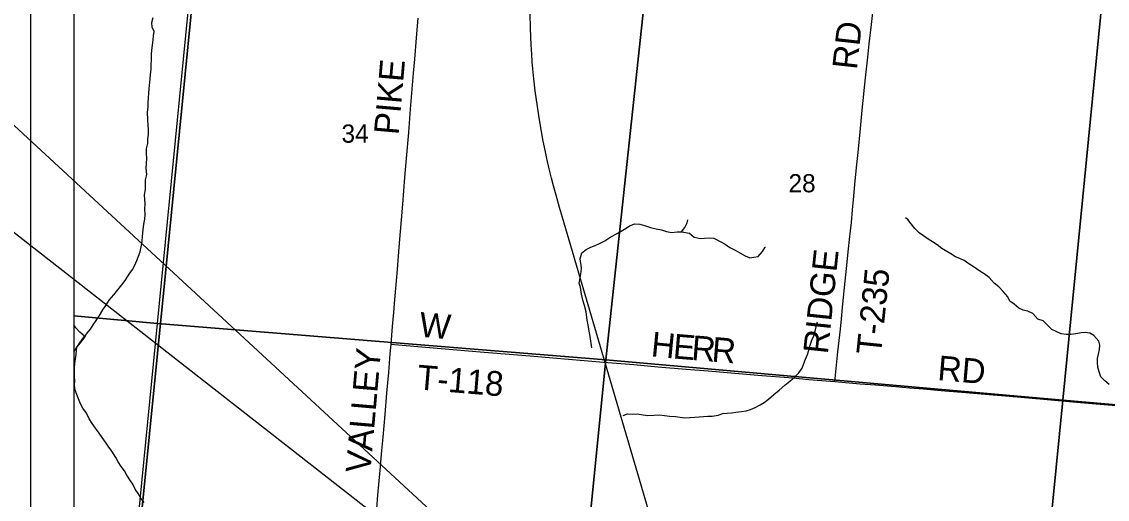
# Model space of a CAD drawing. Extents: x 831 to 1552, y 430 to 870.
# Drawn here: x 943.37 to 993.28, y 692.99 to 714.97 of the extents above; entities that cross this region are included whole.
import ezdxf

# ---------------------------------------------------------------- set-up
doc = ezdxf.new("R2010")
doc.units = 0
for name, color, linetype in [('GM_X_Corporation', 7, 'Continuous'), ('GM_X_County_Road', 7, 'Continuous'), ('GM_X_County_Road_Text', 7, 'Continuous'), ('GM_X_Major_River', 7, 'Continuous'), ('GM_X_Minor_River', 7, 'Continuous'), ('GM_X_Rail_Line', 7, 'Continuous'), ('GM_X_Section_Text', 7, 'Continuous'), ('GM_X_Township_Road', 7, 'Continuous'), ('GM_X_Township_Road_Text', 7, 'Continuous'), ('SH_Data', 7, 'Continuous'), ('SH_Text', 7, 'Continuous')]:
    doc.layers.add(name, color=color, linetype=linetype)

msp = doc.modelspace()

# ---------------------------------------------------------------- linework, layer by layer
at = {"layer": 'GM_X_Corporation'}
msp.add_lwpolyline([(957.479, 781.045), (956.56, 771.006), (955.451, 760.717), (953.653, 740.871), (952.689, 730.885), (949.971, 703.401), (947.763, 681.071), (945.766, 658.183), (945.766, 650.938), (1069.909, 650.938), (1070.34, 654.531), (1072.813, 675.454), (1078.126, 715.958), (1081.227, 740.59), (1081.766, 744.853), (1081.766, 786.938)], dxfattribs=at)
for points in [[(945.766, 741.831), (945.766, 658.183), (947.763, 681.071), (949.971, 703.401), (952.689, 730.885), (953.653, 740.871)], [(945.766, 721.457), (945.766, 701.429), (949.612, 701.081), (951.55, 720.891)], [(972.322, 718.961), (970.228, 699.411), (949.612, 701.081), (951.55, 720.891)], [(993.147, 717.069), (991.236, 697.554), (970.228, 699.411), (972.322, 718.961)], [(993.147, 717.069), (1013.944, 715), (1011.587, 695.769), (991.236, 697.554)], [(945.766, 701.429), (945.766, 681.274), (947.656, 681.105), (949.612, 701.081)], [(970.228, 699.411), (968.2, 679.179), (947.656, 681.105), (949.612, 701.081)], [(970.228, 699.411), (991.236, 697.554), (989.239, 677.411), (968.2, 679.179)], [(1011.587, 695.769), (1009.676, 675.38), (989.239, 677.411), (991.236, 697.554)]]:
    msp.add_lwpolyline(points, close=True, dxfattribs=at)
at = {"layer": 'GM_X_County_Road'}
for points in [[(960.352, 700.134), (960.421, 700.945), (960.476, 701.589), (960.526, 702.183), (960.597, 703.038), (960.64, 703.571), (960.72, 704.599), (960.883, 706.572), (960.985, 707.802), (961.06, 708.677), (961.159, 709.877), (961.244, 710.945), (961.379, 712.6), (961.435, 713.237), (961.517, 714.233), (961.591, 715.127)], [(959.689, 692.563), (959.744, 693.182), (959.843, 694.327), (959.924, 695.237), (959.982, 695.856), (960.07, 696.896), (960.155, 697.874), (960.239, 698.828), (960.314, 699.682), (960.352, 700.134)]]:
    msp.add_lwpolyline(points, dxfattribs=at)
at = {"layer": 'GM_X_Major_River'}
for points in [[(945.904, 699.985), (946.076, 700.198), (946.234, 700.399), (946.353, 700.6), (946.527, 700.823), (946.654, 701.024), (946.797, 701.218), (946.94, 701.456), (947.092, 701.71), (947.242, 701.911), (947.394, 702.157), (947.606, 702.401), (947.794, 702.623), (947.976, 702.853), (948.118, 703.062), (948.302, 703.352), (948.46, 703.56), (948.564, 703.77), (948.662, 703.987), (948.81, 704.377), (948.862, 704.603), (948.9, 704.86), (948.915, 705.102), (948.946, 705.39), (948.984, 705.647), (949.022, 705.888), (949.043, 706.1), (949.035, 706.336), (949.05, 706.593), (949.026, 706.791), (949.016, 706.996), (949.062, 707.253), (949.054, 707.495), (949.052, 707.693), (949.113, 707.941), (949.091, 708.222), (949.097, 708.45), (949.12, 708.692), (949.111, 708.897), (949.11, 709.124), (949.17, 709.358), (949.169, 709.585), (949.198, 709.781), (949.197, 710.001), (949.18, 710.214), (949.164, 710.449), (949.145, 710.806), (949.174, 711.04), (949.187, 711.229), (949.202, 711.464), (949.208, 711.676), (949.222, 711.88), (949.266, 712.334), (949.287, 712.538), (949.317, 712.772), (949.315, 712.961), (949.337, 713.211), (949.329, 713.453), (949.35, 713.657), (949.373, 713.892), (949.41, 714.133), (949.431, 714.322), (949.452, 714.518), (949.367, 714.71), (949.343, 714.93), (949.41, 715.163)], [(945.904, 699.985), (945.856, 699.947), (945.766, 699.759)], [(948.994, 692.849), (948.848, 693.043), (948.725, 693.26), (948.587, 693.462), (948.472, 693.685), (948.342, 693.894), (948.204, 694.096), (948.088, 694.305), (947.935, 694.507), (947.804, 694.716), (947.696, 694.909), (947.508, 695.211), (947.34, 695.429), (947.224, 695.622), (947.071, 695.832), (946.925, 696.041), (946.757, 696.259), (946.604, 696.484), (946.474, 696.693), (946.345, 696.947), (946.17, 697.188), (946.069, 697.381), (945.985, 697.611), (945.9, 697.819), (945.822, 698.019), (945.798, 698.224), (945.804, 698.444), (945.795, 698.642), (945.801, 698.855), (945.792, 699.045), (945.813, 699.242), (945.834, 699.454), (945.87, 699.658), (945.884, 699.847), (945.904, 699.985)]]:
    msp.add_lwpolyline(points, dxfattribs=at)
at = {"layer": 'GM_X_Minor_River'}
for points in [[(973.697, 705.303), (973.85, 705.505), (973.955, 705.706), (973.989, 705.85)], [(993.355, 698.278), (993.163, 698.435), (992.986, 698.631), (992.902, 698.861), (992.847, 699.075), (992.831, 699.281), (992.829, 699.471), (992.865, 699.675), (992.917, 699.879), (992.93, 700.076), (992.883, 700.275), (992.662, 700.524), (992.468, 700.629), (992.264, 700.665), (992.074, 700.656), (991.83, 700.61), (991.616, 700.571), (991.381, 700.57), (991.154, 700.607), (990.93, 700.713), (990.728, 700.81), (990.514, 701.021), (990.322, 701.201), (990.081, 701.277), (989.846, 701.534), (989.629, 701.655), (989.411, 701.699), (989.216, 701.789), (988.994, 701.977), (988.793, 702.112), (988.7, 702.305), (988.494, 702.546), (988.289, 702.773), (988.073, 702.938), (987.853, 703.195), (987.608, 703.37), (987.414, 703.489), (987.117, 703.711), (986.915, 703.823), (986.7, 703.973), (986.498, 704.078), (986.303, 704.152), (986.086, 704.28), (985.892, 704.392), (985.669, 704.535), (985.454, 704.693), (985.238, 704.836), (985.044, 704.963), (984.828, 705.114), (984.62, 705.249), (984.421, 705.452), (984.26, 705.661), (984.107, 705.863), (984.003, 705.942)], [(969.581, 699.96), (969.505, 700.486), (969.447, 700.822), (969.414, 701.013), (969.36, 701.234), (969.311, 701.615), (969.243, 701.906), (969.167, 702.159), (969.099, 702.426), (969.056, 702.746), (969.001, 702.938), (969.046, 703.179), (969.084, 703.451), (969.098, 703.648), (969.049, 704.06), (969.118, 704.338), (969.312, 704.492), (969.528, 704.592), (969.735, 704.677), (969.927, 704.762), (970.181, 704.884), (970.445, 705.073), (970.738, 705.224), (971.085, 705.419), (971.333, 705.594), (971.548, 705.671), (971.783, 705.649), (972.001, 705.597), (972.279, 705.505), (972.535, 705.437), (972.784, 705.384), (973.017, 705.317), (973.236, 705.272), (973.495, 705.295), (973.723, 705.304), (974.063, 705.241), (974.277, 705.06), (974.556, 704.999), (974.761, 705), (974.974, 705.017), (975.187, 705.01), (975.508, 704.834), (975.71, 704.73), (975.925, 704.571), (976.172, 704.45), (976.389, 704.338), (976.627, 704.194), (976.837, 704.097), (977.028, 704.137), (977.226, 704.161), (977.43, 704.398), (977.542, 704.6), (977.557, 704.592)], [(945.904, 699.985), (946.252, 700.505), (946.045, 700.678), (945.854, 700.888), (945.766, 701.018)], [(971.022, 696.848), (971.222, 696.926), (971.426, 696.912), (971.662, 696.92), (971.934, 696.874), (972.153, 696.845), (972.434, 696.867), (972.685, 696.875), (972.912, 696.845), (973.154, 696.823), (973.419, 696.808), (973.638, 696.763), (973.85, 696.734), (974.078, 696.75), (974.306, 696.774), (974.512, 696.791), (974.717, 696.8), (974.907, 696.81), (975.112, 696.819), (975.379, 696.864), (975.601, 696.933), (975.807, 696.95), (976.005, 696.967), (976.195, 697), (976.439, 697.038), (976.675, 697.061), (976.867, 697.117), (977.09, 697.216), (977.313, 697.331), (977.506, 697.447), (977.708, 697.601), (977.942, 697.815), (978.191, 698.02), (978.448, 698.248), (978.681, 698.431), (978.899, 698.607), (979.102, 698.806), (979.245, 699.022), (979.327, 699.24), (979.409, 699.435), (979.499, 699.653), (979.55, 699.849), (979.594, 700.045), (979.7, 700.308), (979.79, 700.518), (979.849, 700.729), (979.893, 700.933), (979.945, 701.129), (979.96, 701.151)]]:
    msp.add_lwpolyline(points, dxfattribs=at)
at = {"layer": 'GM_X_Rail_Line'}
msp.add_lwpolyline([(972.42, 691.703), (968.237, 705.956), (968.094, 706.422), (967.936, 706.98), (967.823, 707.413), (967.729, 707.775), (967.624, 708.2), (967.513, 708.666), (967.429, 709.059), (967.346, 709.468), (967.265, 709.914), (967.156, 710.545), (967.074, 711.06), (966.978, 711.781), (966.914, 712.341), (966.869, 712.792), (966.841, 713.121), (966.814, 713.476), (966.786, 713.905), (966.754, 714.671), (966.737, 715.348)], dxfattribs=at)
at = {"layer": 'GM_X_Township_Road'}
for points in [[(980.75, 698.407), (980.765, 698.546), (980.893, 699.77), (981.005, 700.82), (981.051, 701.29), (981.124, 701.982), (981.23, 703.033), (981.293, 703.613), (981.384, 704.515), (981.425, 704.948), (981.466, 705.344), (981.509, 705.727), (981.566, 706.308), (981.61, 706.766), (981.674, 707.471), (981.753, 708.263), (981.823, 708.955), (981.929, 710.055), (982.013, 710.896), (982.165, 712.382), (982.264, 713.339), (982.336, 713.944), (982.435, 714.838), (982.536, 715.789)], [(960.352, 700.134), (960.503, 700.121), (963.189, 699.89), (964.625, 699.762), (966.743, 699.585), (967.782, 699.5), (969.231, 699.372), (970.122, 699.295), (971.509, 699.188), (972.61, 699.089), (973.91, 698.98), (974.924, 698.895), (977.211, 698.696), (978.819, 698.576), (979.549, 698.509), (980.75, 698.407)], [(980.75, 698.407), (981.405, 698.352), (981.912, 698.309), (982.619, 698.255), (983.535, 698.177), (984.178, 698.121), (984.822, 698.068), (985.305, 698.027), (985.8, 697.985), (986.593, 697.919), (987.657, 697.828), (988.784, 697.731), (990.344, 697.597), (991.865, 697.465), (993.139, 697.352), (994.982, 697.193), (997.458, 696.978), (998.82, 696.862), (1000.021, 696.769), (1000.764, 696.714), (1001.33, 696.666), (1001.494, 696.652)]]:
    msp.add_lwpolyline(points, dxfattribs=at)
at = {"layer": 'SH_Data'}
for p, q in [((943.766, 788.938), (943.766, 648.938)), ((945.766, 786.938), (945.766, 650.938))]:
    msp.add_line(p, q, dxfattribs=at)
at = {"layer": 'SH_Text'}
msp.add_lwpolyline([(977.418, 678.354), (911.466, 739.393), (911.466, 729.958)], close=True, dxfattribs=at)

# ---------------------------------------------------------------- texts
at = {"layer": 'GM_X_County_Road_Text'}
for s, rotation, p in [('PIKE', 85.0575, (960.692, 709.734)), ('VALLEY', 85.022, (959.392, 694.173))]:
    msp.add_text(s, height=1.1364, rotation=rotation, dxfattribs=at).set_placement(p)
at = {"layer": 'GM_X_Section_Text'}
for s, p in [('34', (958.071, 709.402)), ('28', (978.621, 707.118))]:
    msp.add_text(s, height=0.8371, rotation=0, dxfattribs=at).set_placement(p)
at = {"layer": 'GM_X_Township_Road_Text'}
for s, height, rotation, p in [('RD', 1.1364, 83.6073, (981.76, 712.734)), ('RIDGE', 1.1364, 84.001, (980.426, 699.647)), ('T-235', 1.1364, 84.123, (982.867, 699.605)), ('W', 1.136, 354.9366, (961.61, 700.479)), ('H', 1.136, 354.4032, (972.268, 699.576)), ('E', 1.136, 355.3054, (973.282, 699.477)), ('R', 1.136, 355.3308, (974.13, 699.407)), ('R', 1.136, 355.3268, (975.06, 699.332)), ('RD', 1.1364, 355.0738, (985.443, 698.479)), ('T-118', 1.1364, 355.2365, (961.515, 698.053))]:
    msp.add_text(s, height=height, rotation=rotation, dxfattribs=at).set_placement(p)

doc.saveas('drawing.dxf')
